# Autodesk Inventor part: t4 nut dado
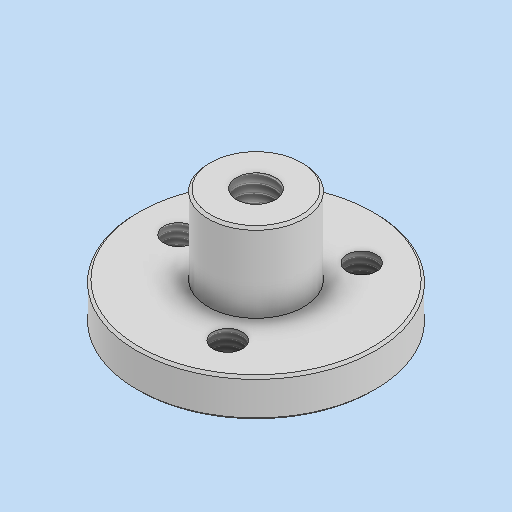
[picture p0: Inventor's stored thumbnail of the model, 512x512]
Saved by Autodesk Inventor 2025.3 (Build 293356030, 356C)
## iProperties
Created: 2025-12
Part Number: t4 nut dado
Material: Generico
Document SubType Name: Modeling
Designer: R5800u
Density: 1 g/cm^3
Appearance: Default
Author: R5800u
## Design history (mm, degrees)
sketch "Schizzo1"
  geometry: L1 (0, 0)-(10, 0); L2 (10, 0)-(10, 3.2); L3 (10, 3.2)-(4, 3.2); L4 (4, 3.2)-(4, 9.8); L5 (4, 9.8)-(0, 9.8); L6 (0, 9.8)-(0, 0)
  constraints: 12 end point, 4 perpendicular, 1 horizontal, 1 vertical
  dimensions: "d0" = 10 distance of L1.start L1.end; "d1" = 3.2 distance of L1.end L2.end; "d2" = 6 distance of L2.end L3.end; "d3" = 6.6 distance of L3.end L4.end
revolve "Rivoluzione1" sketch "Schizzo1" stored, may be unused: angle "d4" = 90 deg
sketch "Schizzo2"
  geometry: C1 r 4 at (0, 0) reference; 2 further points
  constraints: 1 coincident
hole "Foro1" sketch "Schizzo2" at (0, 0) diameter "d5" = 3.242; stored, may be unused: countersink angle "d9" = 90 deg, drill point angle "d11" = 118 deg; dims "d6" = 12, "d7" = 13, "d8" = 3.4, "d10" = 8
chamfer "Smusso1" distance "d12" = 0.2; stored, may be unused: second distance "d13" = 2, angle "d14" = 45 deg
sketch "Schizzo3"
  geometry: 1 further point
sketch "Schizzo4" dims "d15" = 13
  geometry: 3 further points
  constraints: 1 coincident, 1 horizontal alignment, 2 other
hole "Foro2" sketch "Schizzo4" at (-6.5, 0) diameter "d16" = 2.459; stored, may be unused: countersink angle "d20" = 90 deg, drill point angle "d22" = 118 deg; dims "d17" = 6, "d18" = 11, "d19" = 2.6, "d21" = 8
pattern_circular "Serie circolare1" dims angle "d24" = 360 deg
node "Solido1"
